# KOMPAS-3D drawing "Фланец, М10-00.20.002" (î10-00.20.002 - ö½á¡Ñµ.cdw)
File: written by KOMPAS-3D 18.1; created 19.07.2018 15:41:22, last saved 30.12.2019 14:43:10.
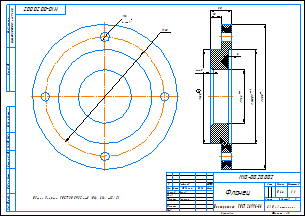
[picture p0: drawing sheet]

Sheet 1: A3, landscape

Document properties: Автор: Мирончук; Организация: Мирончук; Полное имя файла: М10-00.20.002 - Фланец.m3d; Масса: 0.439491

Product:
- Part/product: Фланец  | designation М10-00.20.002
    Материал: Полипропилен  ГОСТ 26996-86 (density 900 kg/m3)
    Масса: 0.439491
    Раздел спецификации: Детали
    Форматы листов документа: A3
    Примечание: габ. 71, 80
    source file: М10-00.20.002 - Фланец.cdw

Title block, sheet 1: Наименование: Фланец; designation: М10-00.20.002; Материал: Полипропилен  ГОСТ 26996-86; Масса: 0,44; scale: 1:1; Количество листов документа: 1; organisation: ЗАО «Астерион»; Форматы листов документа: A3; stored path: Z:\Магна\Магна Ins\Магна ins 10\М10-00.00.000\3Д\М10-00.20.002 - Фланец.cdw; Разработал: Милов; Т. контр.: Лучихин

Views: Вид 1, Местный разрез 1, Спереди, Проекционный вид 2
Referenced files in Z:\Магна\Магна Ins\Магна ins 10\М10-00.00.000\3Д\: М10-00.20.002 - Фланец.m3d
Referenced files in D:\Magna\Магна Ins\Магна ins 10\М10-00.00.000\3Д\: М10-00.20.002 - Фланец.m3d
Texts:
  М10-00.20.000 дв. габ 71, 80
  Лифлянд
Dimensions and other numbers on the sheet: 130; 73,8; 200; 15; 30; 5; 4; 1; 165; 12; 4 отв.; 1:1; 0,44; 22.07.2019

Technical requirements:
  Общие допуски ГОСТ 30893.2-mK (H14, h14,  t2/2).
